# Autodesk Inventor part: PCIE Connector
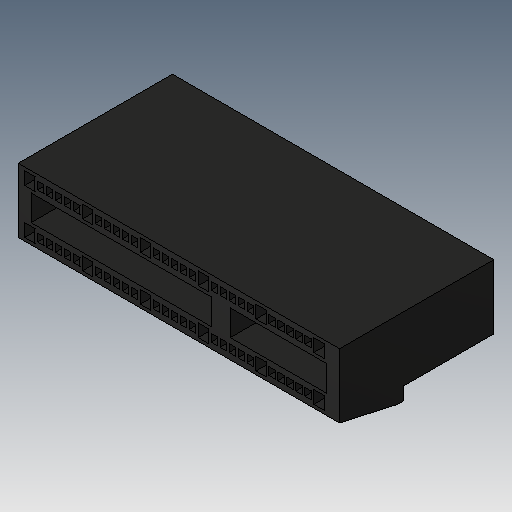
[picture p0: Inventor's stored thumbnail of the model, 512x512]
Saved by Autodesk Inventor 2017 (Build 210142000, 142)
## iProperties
Created: 2005-12
Part Number: PCIE Connector
Material: Generic
Document SubType Name: Modeling
Designer: DanielSeverino
Density: 1 g/cm^3
Appearance: Default
Author: DanielSeverino
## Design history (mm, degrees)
feature "Solid1"
body "Solid2"
